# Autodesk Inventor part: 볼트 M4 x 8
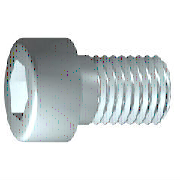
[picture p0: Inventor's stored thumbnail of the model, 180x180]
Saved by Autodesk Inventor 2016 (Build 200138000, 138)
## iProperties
IsCustomPart: 1
Created: 2012-02
Part Number: 볼트 M4 x 8
Material: 스테인리스강
Description: 6각 소켓 머리 캡 나사
Document SubType Name: Modeling
Standard: ISO 4762
Designer: mduedu
Standard Revision: Fourth edition 2004-03-01
Standards Organization: ISO
Language: ko-KR
Size Designation: M4 x 8
Categories: <MemberInstance><Categories><Category DisplayName="조임쇠" InternalName="e4da775c-781d-43d5-af7c-5136215cf5a6" Mnemonic="FSTN"><Category DisplayName="볼트" InternalN
Density: 7.75 g/cm^3
Appearance: 반광택
Author: mduedu
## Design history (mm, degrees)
sketch "스케치1"
  geometry: L1 (-1, 0)-(8, 0); L2 (8, 0)-(8, 2); L3 (8, 2)-(1.75, 2); L4 (1.75, 2)-(1.32, 2); L5 (1.32, 2)-(0, 2); L6 (0, 2)-(0, 3.5); L7 (0, 3.5)-(-4, 3.5); L8 (-4, 3.5)-(-4, 1.732); L9 (-4, 1.732)-(-2, 1.732); L10 (-2, 1.732)-(-1, 0); L11 (-6.4, 0)-(10.4, 0) reference; L12 (0, -0.7)-(0, 4.2) reference; L13 (1.75, 2)-(0, 2)
  constraints: 22 end point, 6 parallel, 2 collinear, 2 perpendicular, 1 horizontal, 1 point on line
  dimensions: "d1" = 6.25 distance from line of L3.end L2 (= GEL); "d2" = 0.42952 distance of L4.end L3.end (computed from GAL); "d3" = 4 distance between parallel lines of L8 L6 (= KOH); "d4" = 2 distance of L8.end L9.end (= INTI); "d5" = 60 deg angle of L10 L1; "d6" = 4 diameter of L3 L1 (= GD); "d7" = 4 diameter of L5 L1 (= BDM); "d8" = 3.4641 diameter of L9 L1 (= 1.1547 x SW); "d9" = 7 diameter of L7 L1 (= KOD); "d26" = 8 distance between parallel lines of L12 L2 (= NLG)
revolve "본체" sketch "스케치1" stored, may be unused: angle "d10" = 90 deg
sketch "스케치2"
  geometry: L1 (0, -4.9)-(0, 4.9) reference; L2 (-4.9, 0)-(4.9, 0) reference; L3 (1.732, 0)-(0.866, -1.5); L4 (0.866, -1.5)-(-0.866, -1.5); L5 (-0.866, -1.5)-(-1.732, 0); L6 (-1.732, 0)-(-0.866, 1.5); L7 (-0.866, 1.5)-(0.866, 1.5); L8 (0.866, 1.5)-(1.732, 0); 2 further points
  constraints: 12 end point, 1 coincident, 1 horizontal alignment, 1 point on line, 12 other
extrude "슬롯" join sketch "스케치2" stored distance "d11" = 10; taper "d12" = 0 deg
workplane "Work Plane1"
fillet "Fillet2" dims "d30" = 0.1 (= R)
body "Solid1"
fillet "모깎기1" dims "d17" = 0.4 (= RR)
feature "스레드" dims "d13" = 6.25 (= GEL), "d14" = 0
chamfer "모따기1" distance "d15" = 0.42941 (= -0.5 x SPD + 0.5 x GD); stored, may be unused: second distance "d16" = 0.42941 (= GUL), angle "d27" = 45 deg
other parameters: "GD" = 4 [user parameter; used in 2 equation terms], "NLG" = 8 [user parameter; used in 1 equation term], "GEL" = 6.25 [user parameter; used in 2 equation terms], "KOD" = 7 [user parameter; used in 1 equation term], "KOH" = 4 [user parameter; used in 1 equation term], "INTI" = 2 [user parameter; used in 1 equation term], "GAL" = 0.42941 (= 0.61345 x PTC) [user parameter; used in 1 equation term], "GUL" = 0.42941 (= 0.61345 x PTC) [user parameter; used in 1 equation term], "BDM" = 4 (= NND) [user parameter; used in 1 equation term], "SW" = 3 [user parameter; used in 2 equation terms], "RR" = 0.4 [user parameter; used in 1 equation term], "SPD" = 3.14117 (= NND - 1.2269 x PTC) [user parameter; used in 1 equation term], "d19" = 0, "d28" = 0, "d29" = 0, "R" = 0.1 [user parameter; used in 1 equation term], "TOA" = 30 deg [user parameter], "GD1" = 3.14117 (= THREADDIA - 1.2269 x PTC) [user parameter], "THREADDIA" = 4 [user parameter; used in 1 equation term], "FAWI" = 45 deg [user parameter], "TPU" = 14.28571 (computed from PTC) [user parameter], "PTC" = 0.7 [user parameter; used in 5 equation terms], "NND" = 4 [user parameter; used in 2 equation terms], "E0" = 3.465 (= 1.155 x SW) [user parameter]
